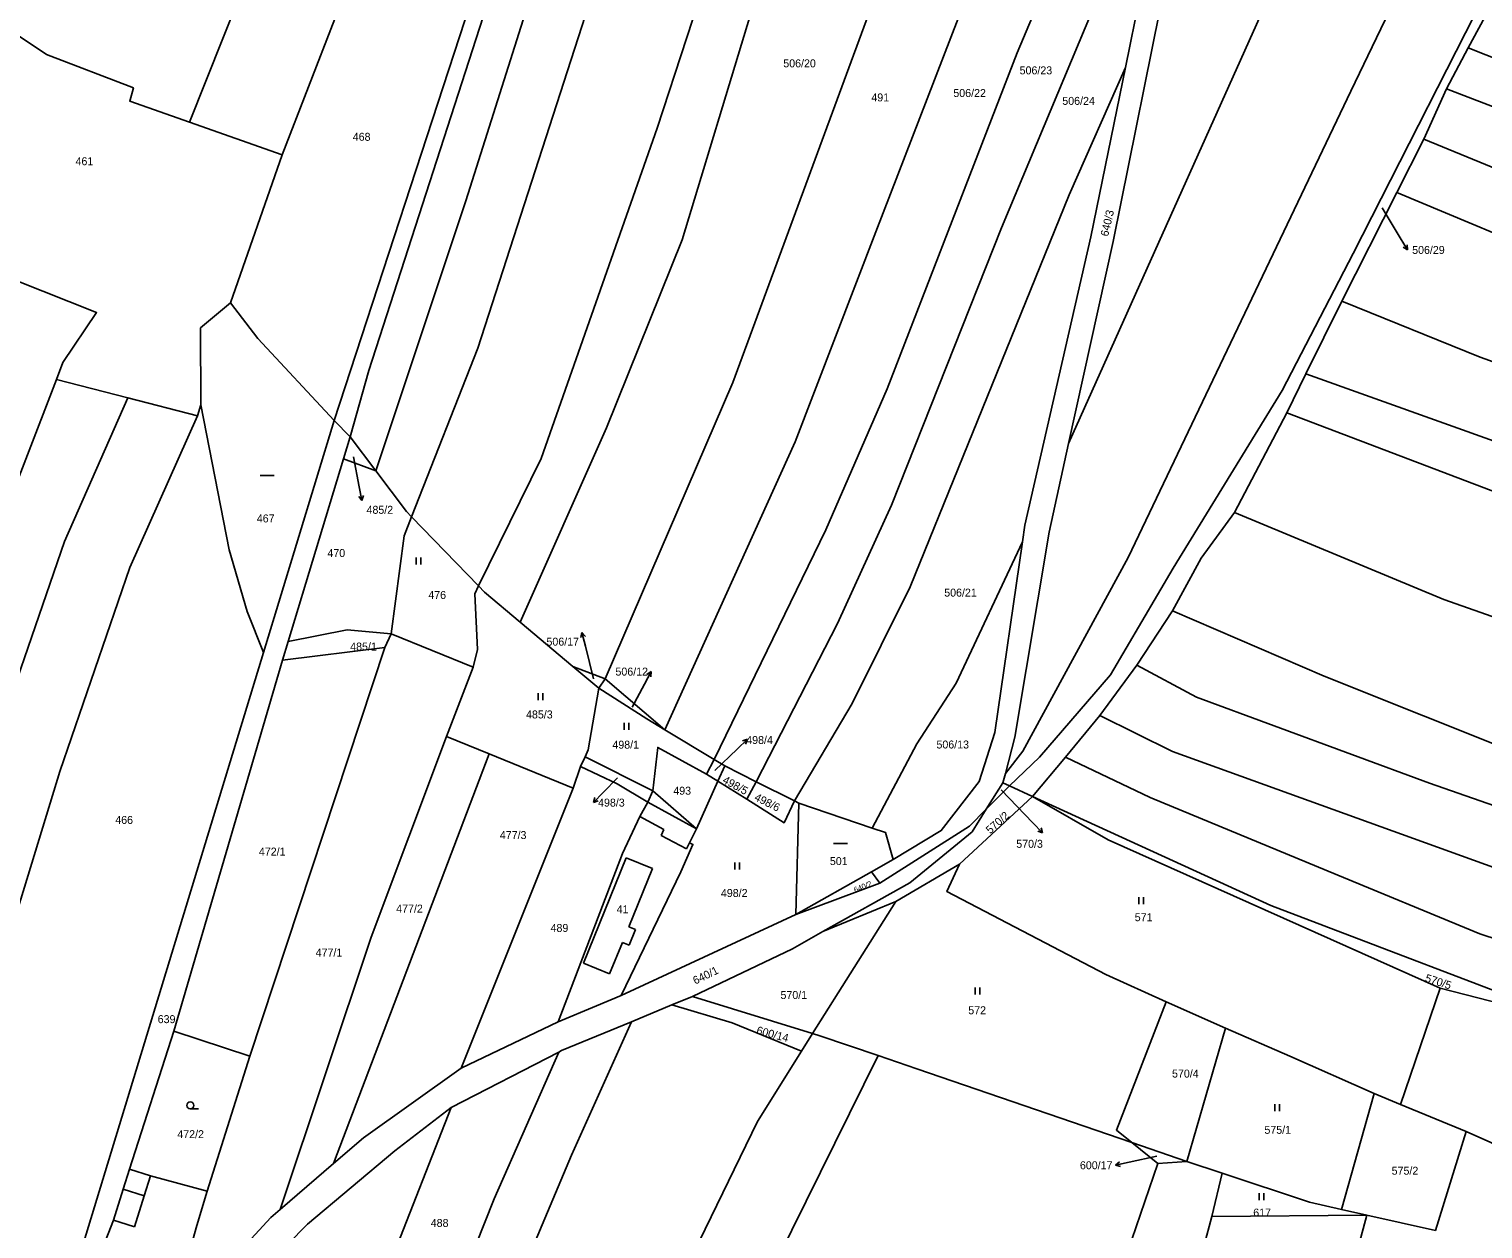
# Model space of a CAD drawing. Extents: x -746176 to -739709, y -1128407 to -1124482.
# Drawn here: x -742784.8 to -742474.2, y -1127139.9 to -1126883.6 of the extents above; entities that cross this region are included whole.
import ezdxf

# ---------------------------------------------------------------- set-up
doc = ezdxf.new("R2010")
doc.units = 0
for name, color, linetype in [('Hranice parcel', 7, 'Continuous'), ('Parcelní čísla', 7, 'Continuous'), ('Pop  PČ popisy', 7, 'Continuous'), ('Vnitřní kresba', 7, 'Continuous'), ('Značky kultur', 7, 'Continuous')]:
    doc.layers.add(name, color=color, linetype=linetype)

msp = doc.modelspace()

# ---------------------------------------------------------------- linework, layer by layer
at = {"layer": 'Hranice parcel'}
for p, q in [((-742550.57, -1126891.8), (-742539.32, -1126836.74)), ((-742465.86, -1126866.52), (-742477.38, -1126887.58)), ((-742481.95, -1126896.36), (-742477.38, -1126887.58)), ((-742486.79, -1126907.12), (-742481.95, -1126896.36)), ((-742730.7, -1126910.48), (-742750.49, -1126903.46)), ((-742492.57, -1126918.49), (-742486.79, -1126907.12)), ((-742741.76, -1126942.06), (-742730.7, -1126910.48)), ((-742504.35, -1126941.71), (-742492.57, -1126918.49)), ((-742512.02, -1126957.27), (-742504.35, -1126941.71)), ((-742516.09, -1126965.6), (-742512.02, -1126957.27)), ((-742778.92, -1126958.45), (-742763.72, -1126962.33)), ((-742763.72, -1126962.33), (-742748.81, -1126966.24)), ((-742748.81, -1126966.24), (-742748.07, -1126963.89)), ((-742719.6, -1126967.23), (-742734.68, -1127016.73)), ((-742716.17, -1126970.68), (-742719.6, -1126967.23)), ((-742527.24, -1126986.86), (-742516.09, -1126965.6)), ((-742717.6, -1126975.4), (-742716.17, -1126970.68)), ((-742710.71, -1126977.95), (-742716.17, -1126970.68)), ((-742729.41, -1127014.42), (-742717.6, -1126975.4)), ((-742710.71, -1126977.95), (-742717.6, -1126975.4)), ((-742688.81, -1127002.53), (-742703.1, -1126987.76)), ((-742668.63, -1127019.74), (-742679.87, -1127010.3)), ((-742548.14, -1127019.47), (-742540.51, -1127007.89)), ((-742707.46, -1127012.77), (-742708.78, -1127015.67)), ((-742707.46, -1127012.77), (-742689.92, -1127019.87)), ((-742734.68, -1127016.73), (-742781.25, -1127169.22)), ((-742737.64, -1127102.99), (-742708.78, -1127015.67)), ((-742730.63, -1127018.43), (-742729.41, -1127014.42)), ((-742708.78, -1127015.67), (-742730.63, -1127018.43)), ((-742730.63, -1127018.43), (-742753.9, -1127097.67)), ((-742695.58, -1127034.67), (-742689.92, -1127019.87)), ((-742663.1, -1127024.39), (-742668.63, -1127019.74)), ((-742661.75, -1127022.4), (-742668.63, -1127019.74)), ((-742556.03, -1127030.18), (-742548.14, -1127019.47)), ((-742661.75, -1127022.4), (-742663.1, -1127024.39)), ((-742661.75, -1127022.4), (-742648.95, -1127033.28)), ((-742563.37, -1127039.11), (-742556.03, -1127030.18)), ((-742686.48, -1127038.39), (-742695.58, -1127034.67)), ((-742638.43, -1127039.61), (-742648.95, -1127033.28)), ((-742719.74, -1127125.92), (-742686.48, -1127038.39)), ((-742668.53, -1127045.71), (-742686.48, -1127038.39)), ((-742666.98, -1127041.09), (-742668.53, -1127045.71)), ((-742666.98, -1127041.09), (-742666.02, -1127039.02)), ((-742666.02, -1127039.02), (-742651.5, -1127046.32)), ((-742640.1, -1127042.71), (-742638.43, -1127039.61)), ((-742636.14, -1127040.99), (-742638.43, -1127039.61)), ((-742637.62, -1127044.26), (-742636.14, -1127040.99)), ((-742629.44, -1127044.36), (-742636.14, -1127040.99)), ((-742570.42, -1127047.48), (-742563.37, -1127039.11)), ((-742637.62, -1127044.26), (-742642.23, -1127054.43)), ((-742637.62, -1127044.26), (-742640.1, -1127042.71)), ((-742631.47, -1127048.12), (-742637.62, -1127044.26)), ((-742631.47, -1127048.12), (-742629.44, -1127044.36)), ((-742621.26, -1127048.47), (-742629.44, -1127044.36)), ((-742576.74, -1127044.58), (-742580.29, -1127050.24)), ((-742576.22, -1127042.62), (-742576.74, -1127044.58)), ((-742576.74, -1127044.58), (-742575.31, -1127045.24)), ((-742668.53, -1127045.71), (-742692.49, -1127105.57)), ((-742651.5, -1127046.32), (-742652.6, -1127048.7)), ((-742642.23, -1127054.43), (-742651.5, -1127046.32)), ((-742586.05, -1127061.99), (-742570.42, -1127047.48)), ((-742575.31, -1127045.24), (-742580.29, -1127050.24)), ((-742575.31, -1127045.24), (-742570.42, -1127047.48)), ((-742620.33, -1127048.94), (-742621.26, -1127048.47)), ((-742620.96, -1127072.73), (-742620.33, -1127048.94)), ((-742620.33, -1127048.94), (-742604.64, -1127054.26)), ((-742600.22, -1127061), (-742604.82, -1127063.6)), ((-742599.65, -1127069.95), (-742586.05, -1127061.99)), ((-742604.82, -1127063.6), (-742620.96, -1127072.73)), ((-742603.07, -1127066.02), (-742620.96, -1127072.73)), ((-742603.07, -1127066.02), (-742604.82, -1127063.6)), ((-742658.33, -1127090.03), (-742620.96, -1127072.73)), ((-742617.44, -1127098.12), (-742599.65, -1127069.95)), ((-742599.65, -1127069.95), (-742615.18, -1127076.38)), ((-742647.45, -1127092.03), (-742643.05, -1127090.21)), ((-742643.05, -1127090.21), (-742617.44, -1127098.12)), ((-742529.16, -1127097), (-742541.89, -1127091.38)), ((-742483.35, -1127088.47), (-742491.78, -1127113.29)), ((-742483.35, -1127088.47), (-742452.64, -1127096.27)), ((-742656.1, -1127095.61), (-742647.45, -1127092.03)), ((-742763.33, -1127127.12), (-742753.9, -1127097.67)), ((-742753.9, -1127097.67), (-742737.64, -1127102.99)), ((-742692.49, -1127105.57), (-742671.78, -1127095.63)), ((-742537.43, -1127125.45), (-742529.16, -1127097)), ((-742617.44, -1127098.12), (-742619.79, -1127101.89)), ((-742737.64, -1127102.99), (-742746.73, -1127131.84)), ((-742694.65, -1127113.94), (-742671.65, -1127102.1)), ((-742504.39, -1127135.7), (-742497.42, -1127110.95)), ((-742497.42, -1127110.95), (-742491.78, -1127113.29)), ((-742694.65, -1127113.94), (-742722.13, -1127184.01)), ((-742491.78, -1127113.29), (-742477.79, -1127119.09)), ((-742477.79, -1127119.09), (-742484.3, -1127140.22)), ((-742444.54, -1127133.92), (-742477.79, -1127119.09)), ((-742549.17, -1127121.43), (-742543.65, -1127125.88)), ((-742549.17, -1127121.43), (-742537.43, -1127125.45)), ((-742537.43, -1127125.45), (-742543.65, -1127125.88)), ((-742537.43, -1127125.45), (-742529.93, -1127127.94)), ((-742719.74, -1127125.92), (-742731.14, -1127135.75)), ((-742529.93, -1127127.94), (-742532.11, -1127137.2)), ((-742532.11, -1127137.2), (-742498.96, -1127136.92)), ((-742498.96, -1127136.92), (-742504.39, -1127135.7)), ((-742498.96, -1127136.92), (-742484.3, -1127140.22))]:
    msp.add_line(p, q, dxfattribs=at)
for points in [[(-742561.23, -1126767.89), (-742567.77, -1126783.13), (-742587.89, -1126832.72), (-742634.42, -1126959.12), (-742661.75, -1127022.4)], [(-742679.87, -1127010.3), (-742661.43, -1126968.75), (-742645.29, -1126928.59), (-742630.66, -1126880.5), (-742621.29, -1126852.62), (-742599.04, -1126792.93), (-742588.76, -1126769.25)], [(-742648.95, -1127033.28), (-742621.1, -1126971.78), (-742603.91, -1126926.94), (-742554.63, -1126799.18), (-742540.06, -1126770.15)], [(-742688.81, -1127002.53), (-742675.39, -1126975.35), (-742650.59, -1126904.79), (-742637.92, -1126865.97), (-742628.71, -1126838.73), (-742613.44, -1126798.13), (-742604.44, -1126772.24)], [(-742703.1, -1126987.76), (-742688.91, -1126951.77), (-742648.33, -1126826.13), (-742639.39, -1126803.22), (-742629.18, -1126778.81)], [(-742638.43, -1127039.61), (-742614.56, -1126990.57), (-742601.46, -1126960.43), (-742573.73, -1126888.65), (-742536.1, -1126799.53), (-742527.67, -1126779.74)], [(-742710.71, -1126977.95), (-742691.49, -1126920.27), (-742659.71, -1126819.94), (-742646.21, -1126781.41)], [(-742719.6, -1126967.23), (-742690.51, -1126878.08), (-742694.48, -1126866.91), (-742676.36, -1126812.17), (-742671.59, -1126785.41)], [(-742716.17, -1126970.68), (-742712.23, -1126956.56), (-742687.03, -1126878.58), (-742688.27, -1126869.14), (-742663.45, -1126784.04)], [(-742562.72, -1126972.14), (-742511.64, -1126858.28), (-742475.66, -1126785.18)], [(-742730.7, -1126910.48), (-742713.83, -1126866.81), (-742706.14, -1126831.54), (-742708.37, -1126829.06), (-742696.43, -1126791.7)], [(-742576.22, -1127042.62), (-742572.46, -1127037.81), (-742549.96, -1126996.44), (-742502.42, -1126896.85), (-742478.65, -1126847.35), (-742462.47, -1126810.41), (-742451.42, -1126791.4)], [(-742750.49, -1126903.46), (-742732.76, -1126858.93), (-742706.72, -1126793.58)], [(-742431.72, -1126796.46), (-742469.95, -1126868.69), (-742501.91, -1126931.51), (-742517.1, -1126960.81), (-742540.36, -1126998.76), (-742553.75, -1127021.53), (-742568.92, -1127039.08), (-742575.31, -1127045.24)], [(-742629.44, -1127044.36), (-742612.06, -1127010.59), (-742600.55, -1126985.29), (-742577.05, -1126926.06), (-742554.59, -1126872.35), (-742539.32, -1126836.74)], [(-742750.49, -1126903.46), (-742763.27, -1126898.97), (-742762.5, -1126896.14), (-742781.04, -1126889), (-742799.57, -1126876.62), (-742824.58, -1126865.74)], [(-742541.56, -1126871.36), (-742553.22, -1126928.98), (-742562.72, -1126972.14)], [(-742477.38, -1126887.58), (-742416.04, -1126911.9), (-742348.05, -1126935.25), (-742114.93, -1127013.93), (-742085.96, -1127023.63)], [(-742550.57, -1126891.8), (-742562.56, -1126918.99), (-742596.53, -1127002.73), (-742608.98, -1127027.64), (-742621.26, -1127048.47)], [(-742572.58, -1126993.14), (-742572.06, -1126989.56), (-742557.96, -1126927.95), (-742550.57, -1126891.8)], [(-742089.28, -1127034.5), (-742293.25, -1126965), (-742398.92, -1126928.26), (-742481.95, -1126896.36)], [(-742486.79, -1126907.12), (-742444.87, -1126924.33), (-742397.83, -1126942.23), (-742288.59, -1126978.66), (-742195.26, -1127011.61), (-742092.54, -1127045.19)], [(-742492.57, -1126918.49), (-742455.79, -1126933.86), (-742390.03, -1126957.98), (-742252.16, -1127003.9), (-742129.68, -1127044.77), (-742095.98, -1127056.46)], [(-742778.92, -1126958.45), (-742777.55, -1126954.82), (-742770.36, -1126944.15), (-742810.76, -1126928.12)], [(-742748.07, -1126963.89), (-742748.16, -1126947.44), (-742741.76, -1126942.06)], [(-742741.76, -1126942.06), (-742735.91, -1126949.7), (-742719.6, -1126967.23)], [(-742504.35, -1126941.71), (-742474.75, -1126953.67), (-742378.88, -1126988.04), (-742204.08, -1127046.96), (-742100.58, -1127080.82), (-742076.73, -1127089.67), (-742044, -1127103.72)], [(-742512.02, -1126957.27), (-742426.6, -1126987.75), (-742322.02, -1127023.9), (-742152.02, -1127080.85), (-742092.77, -1127100.11), (-742049.6, -1127117.15)], [(-742842.98, -1127149.74), (-742815.95, -1127061.82), (-742792.49, -1126993.43), (-742778.92, -1126958.45)], [(-742828.27, -1127153.14), (-742812.1, -1127103.89), (-742795.18, -1127045), (-742777.21, -1126993.06), (-742763.72, -1126962.33)], [(-742734.68, -1127016.73), (-742738.19, -1127008), (-742742.04, -1126994.82), (-742748.07, -1126963.89)], [(-742813.25, -1127156.61), (-742778.25, -1127042.21), (-742763.25, -1126998.63), (-742748.81, -1126966.24)], [(-742516.09, -1126965.6), (-742463.84, -1126985.43), (-742374.91, -1127016.27), (-742226.88, -1127065.31), (-742153.9, -1127090.43), (-742091.98, -1127111.83), (-742053.72, -1127127.51)], [(-742562.72, -1126972.14), (-742566.88, -1126991.03), (-742574.16, -1127034.85), (-742576.22, -1127042.62)], [(-742703.1, -1126987.76), (-742704.16, -1126986.66), (-742710.71, -1126977.95)], [(-742707.46, -1127012.77), (-742704.66, -1126991.83), (-742703.1, -1126987.76)], [(-742540.51, -1127007.89), (-742534.38, -1126996.59), (-742527.24, -1126986.86)], [(-742527.24, -1126986.86), (-742482.52, -1127005.44), (-742410.26, -1127030.86), (-742263.45, -1127080.11), (-742124.08, -1127127.86), (-742062.93, -1127150.64)], [(-742572.58, -1126993.14), (-742586.73, -1127023.3), (-742595.13, -1127036.3), (-742604.64, -1127054.26)], [(-742600.22, -1127061), (-742589.93, -1127054.79), (-742581.78, -1127044.3), (-742578.46, -1127033.87), (-742572.58, -1126993.14)], [(-742689.92, -1127019.87), (-742689.01, -1127016.13), (-742689.59, -1127004.26), (-742688.81, -1127002.53)], [(-742679.87, -1127010.3), (-742687.53, -1127003.86), (-742688.81, -1127002.53)], [(-742540.51, -1127007.89), (-742508.14, -1127021.79), (-742465.67, -1127038.76), (-742304.51, -1127093.48), (-742186.57, -1127134.04), (-742101.64, -1127162.49), (-742071.1, -1127173.63)], [(-742729.41, -1127014.42), (-742716.86, -1127011.94), (-742707.46, -1127012.77)], [(-742548.14, -1127019.47), (-742535.36, -1127026.31), (-742485.61, -1127044.66), (-742396.17, -1127075.85), (-742237.29, -1127129.3), (-742102.44, -1127175.98), (-742075.64, -1127186.64)], [(-742663.1, -1127024.39), (-742665.33, -1127037.52), (-742666.02, -1127039.02)], [(-742648.95, -1127033.28), (-742652.83, -1127030.94), (-742663.1, -1127024.39)], [(-742556.03, -1127030.18), (-742540.54, -1127037.88), (-742464.14, -1127065.48), (-742257.87, -1127136.04), (-742181.95, -1127162.82), (-742111.16, -1127186.39), (-742079.42, -1127198.6)], [(-742731.14, -1127135.75), (-742711.74, -1127077.56), (-742695.58, -1127034.67)], [(-742651.5, -1127046.32), (-742650.49, -1127037.02), (-742640.1, -1127042.71)], [(-742652.6, -1127048.7), (-742659.18, -1127044.79), (-742666.98, -1127041.09)], [(-742081.6, -1127209.14), (-742129.12, -1127193.01), (-742202.75, -1127169.34), (-742345.7, -1127119.16), (-742474.83, -1127076.87), (-742507.28, -1127063.47), (-742545.28, -1127047.75), (-742563.37, -1127039.11)], [(-742570.42, -1127047.48), (-742519.53, -1127070.81), (-742452.64, -1127096.27)], [(-742570.42, -1127047.48), (-742554.29, -1127056.77), (-742483.35, -1127088.47)], [(-742652.6, -1127048.7), (-742654.28, -1127051.82), (-742658.01, -1127059.67), (-742671.78, -1127095.63)], [(-742621.26, -1127048.47), (-742623.51, -1127053.12), (-742631.47, -1127048.12)], [(-742615.18, -1127076.38), (-742596.61, -1127065.97), (-742583.33, -1127055.08), (-742580.29, -1127050.24)], [(-742580.29, -1127050.24), (-742583.91, -1127053.87), (-742603.07, -1127066.02)], [(-742658.33, -1127090.03), (-742645.55, -1127063.63), (-742642.98, -1127057.75), (-742643.7, -1127057.4), (-742642.23, -1127054.43)], [(-742604.64, -1127054.26), (-742601.82, -1127055.21), (-742600.22, -1127061)], [(-742586.05, -1127061.99), (-742588.7, -1127067.82), (-742554.78, -1127085.5), (-742541.89, -1127091.38)], [(-742643.05, -1127090.21), (-742621.7, -1127080.04), (-742615.18, -1127076.38)], [(-742671.78, -1127095.63), (-742663.55, -1127092.23), (-742658.33, -1127090.03)], [(-742541.89, -1127091.38), (-742552.48, -1127118.77), (-742549.17, -1127121.43)], [(-742619.79, -1127101.89), (-742634.59, -1127095.86), (-742647.45, -1127092.03)], [(-742656.1, -1127095.61), (-742668.92, -1127124.1), (-742695.82, -1127188.09)], [(-742671.65, -1127102.1), (-742671.07, -1127101.8), (-742656.1, -1127095.61)], [(-742529.16, -1127097), (-742515.45, -1127102.99), (-742497.42, -1127110.95)], [(-742603.37, -1127102.87), (-742615.85, -1127098.61), (-742617.44, -1127098.12)], [(-742706.71, -1127187.05), (-742685.41, -1127133.42), (-742671.65, -1127102.1)], [(-742662.31, -1127190.95), (-742647.78, -1127155.16), (-742629.16, -1127116.92), (-742619.79, -1127101.89)], [(-742644.1, -1127192.22), (-742631.06, -1127158.9), (-742603.37, -1127102.87)], [(-742603.37, -1127102.87), (-742595.15, -1127105.68), (-742549.17, -1127121.43)], [(-742692.49, -1127105.57), (-742713.34, -1127120.39), (-742719.74, -1127125.92)], [(-742738.13, -1127151.87), (-742725.34, -1127138.85), (-742706.66, -1127123.2), (-742694.65, -1127113.94)], [(-742773.17, -1127157.23), (-742769.01, -1127143.81), (-742766.77, -1127137.99), (-742764.69, -1127131.41), (-742763.33, -1127127.12)], [(-742746.73, -1127131.84), (-742758.85, -1127128.54), (-742763.33, -1127127.12)], [(-742543.65, -1127125.88), (-742554.78, -1127158.4), (-742562.37, -1127191.45), (-742566.48, -1127203.04)], [(-742504.39, -1127135.7), (-742511.23, -1127134.16), (-742529.93, -1127127.94)], [(-742746.73, -1127131.84), (-742748.92, -1127139.17), (-742751.52, -1127148.31), (-742756.51, -1127164.2)], [(-742731.14, -1127135.75), (-742733.12, -1127137.46), (-742746.45, -1127151.91), (-742756.51, -1127164.2)], [(-742553.15, -1127238.87), (-742547.82, -1127218.47), (-742536.99, -1127155.61), (-742532.11, -1127137.2)], [(-742523.75, -1127248.38), (-742518.59, -1127225.94), (-742507.29, -1127167.65), (-742498.96, -1127136.92)]]:
    msp.add_lwpolyline(points, dxfattribs=at)
at = {"layer": 'Pop  PČ popisy'}
for p, q in [((-742495.71, -1126921.8), (-742491.86, -1126928.21)), ((-742491.86, -1126928.21), (-742490.31, -1126930.78)), ((-742490.31, -1126930.78), (-742490.4, -1126929.67)), ((-742490.31, -1126930.78), (-742491.26, -1126930.18)), ((-742715.45, -1126974.96), (-742714.25, -1126981.35)), ((-742714.25, -1126981.35), (-742713.68, -1126984.3)), ((-742713.68, -1126984.3), (-742714.36, -1126983.41)), ((-742713.68, -1126984.3), (-742713.38, -1126983.22)), ((-742666.67, -1127012.46), (-742666.91, -1127013.55)), ((-742665.94, -1127015.37), (-742666.67, -1127012.46)), ((-742666.67, -1127012.46), (-742665.94, -1127013.31)), ((-742664.21, -1127022.41), (-742665.94, -1127015.37)), ((-742653.31, -1127023.49), (-742651.9, -1127020.84)), ((-742651.9, -1127020.84), (-742652.81, -1127021.49)), ((-742651.9, -1127020.84), (-742651.93, -1127021.96)), ((-742655.92, -1127028.43), (-742653.31, -1127023.49)), ((-742633.5, -1127037.38), (-742631.34, -1127035.29)), ((-742631.34, -1127035.29), (-742632.41, -1127035.63)), ((-742631.34, -1127035.29), (-742631.71, -1127036.35)), ((-742638.3, -1127041.94), (-742633.5, -1127037.38)), ((-742659.09, -1127043.5), (-742662.15, -1127046.66)), ((-742662.15, -1127046.66), (-742664.23, -1127048.82)), ((-742664.23, -1127048.82), (-742663.9, -1127047.75)), ((-742577.15, -1127046.1), (-742570.34, -1127053.11)), ((-742664.23, -1127048.82), (-742663.18, -1127048.45)), ((-742570.34, -1127053.11), (-742568.26, -1127055.27)), ((-742568.26, -1127055.27), (-742568.59, -1127054.2)), ((-742568.26, -1127055.27), (-742569.31, -1127054.9)), ((-742552.69, -1127126.26), (-742551.81, -1127125.57)), ((-742549.75, -1127125.64), (-742552.69, -1127126.26)), ((-742543.87, -1127124.36), (-742549.75, -1127125.64)), ((-742552.69, -1127126.26), (-742551.6, -1127126.55))]:
    msp.add_line(p, q, dxfattribs=at)
at = {"layer": 'Vnitřní kresba'}
for p, q in [((-742652.6, -1127048.7), (-742642.23, -1127054.43)), ((-742654.28, -1127051.82), (-742649.19, -1127054.59)), ((-742649.73, -1127055.83), (-742649.19, -1127054.59)), ((-742649.73, -1127055.83), (-742644.34, -1127058.7)), ((-742644.34, -1127058.7), (-742643.7, -1127057.4)), ((-742666.37, -1127083.14), (-742657.21, -1127060.61)), ((-742657.21, -1127060.61), (-742651.6, -1127062.89)), ((-742656.67, -1127075.36), (-742651.6, -1127062.89)), ((-742656.67, -1127075.36), (-742655.24, -1127075.94)), ((-742656.59, -1127079.28), (-742655.24, -1127075.94)), ((-742660.76, -1127085.42), (-742658.03, -1127078.7)), ((-742658.03, -1127078.7), (-742656.59, -1127079.28)), ((-742666.37, -1127083.14), (-742660.76, -1127085.42)), ((-742760.21, -1127132.83), (-742758.85, -1127128.54)), ((-742764.69, -1127131.41), (-742760.21, -1127132.83)), ((-742762.29, -1127139.41), (-742760.21, -1127132.83)), ((-742766.77, -1127137.99), (-742765.39, -1127138.43)), ((-742765.39, -1127138.43), (-742762.29, -1127139.41))]:
    msp.add_line(p, q, dxfattribs=at)
at = {"layer": 'Značky kultur'}
for p, q in [((-742735.42, -1126978.93), (-742732.42, -1126978.93)), ((-742702.11, -1126997.97), (-742702.11, -1126996.47)), ((-742701.11, -1126997.97), (-742701.11, -1126996.47)), ((-742676.05, -1127026.97), (-742676.05, -1127025.47)), ((-742675.05, -1127026.97), (-742675.05, -1127025.47)), ((-742657.63, -1127033.26), (-742657.63, -1127031.76)), ((-742656.63, -1127033.26), (-742656.63, -1127031.76)), ((-742612.97, -1127057.56), (-742609.97, -1127057.56)), ((-742634.04, -1127063.11), (-742634.04, -1127061.61)), ((-742633.04, -1127063.11), (-742633.04, -1127061.61)), ((-742547.69, -1127070.53), (-742547.69, -1127069.03)), ((-742546.69, -1127070.53), (-742546.69, -1127069.03)), ((-742582.67, -1127089.81), (-742582.67, -1127088.31)), ((-742581.67, -1127089.81), (-742581.67, -1127088.31)), ((-742750.34, -1127114.24), (-742748.59, -1127114.24)), ((-742518.62, -1127114.73), (-742518.62, -1127113.23)), ((-742517.62, -1127114.73), (-742517.62, -1127113.23)), ((-742522.03, -1127133.76), (-742522.03, -1127132.26)), ((-742521.03, -1127133.76), (-742521.03, -1127132.26))]:
    msp.add_line(p, q, dxfattribs=at)
msp.add_circle((-742750.34, -1127113.49), 0.75, dxfattribs=at)

# ---------------------------------------------------------------- texts
at = {"layer": 'Parcelní čísla'}
for s, p in [('506/20', (-742623.66, -1126891.77)), ('506/23', (-742573.17, -1126893.27)), ('491', (-742604.85, -1126899.05)), ('506/22', (-742587.33, -1126898.11)), ('506/24', (-742564.05, -1126899.79)), ('468', (-742715.64, -1126907.46)), ('461', (-742774.87, -1126912.68)), ('506/29', (-742489.31, -1126931.63)), ('485/2', (-742712.7, -1126987.13)), ('467', (-742736.14, -1126988.97)), ('470', (-742721.05, -1126996.36)), ('476', (-742699.5, -1127005.32)), ('506/21', (-742589.28, -1127004.82)), ('506/17', (-742674.26, -1127015.29)), ('485/1', (-742716.19, -1127016.34)), ('506/12', (-742659.52, -1127021.69)), ('485/3', (-742678.62, -1127030.84)), ('498/1', (-742660.17, -1127037.3)), ('498/4', (-742631.58, -1127036.3)), ('506/13', (-742590.94, -1127037.26)), ('498/3', (-742663.23, -1127049.67)), ('493', (-742647.16, -1127047.13)), ('466', (-742766.38, -1127053.37)), ('477/3', (-742684.22, -1127056.6)), ('570/3', (-742573.89, -1127058.47)), ('472/1', (-742735.69, -1127060.13)), ('501', (-742613.71, -1127062.16)), ('498/2', (-742636.99, -1127068.98)), ('477/2', (-742706.36, -1127072.31)), ('41', (-742659.27, -1127072.46)), ('571', (-742548.58, -1127074.15)), ('489', (-742673.38, -1127076.44)), ('477/1', (-742723.56, -1127081.69)), ('570/1', (-742624.26, -1127090.76)), ('639', (-742757.31, -1127095.92)), ('572', (-742584.14, -1127094.02)), ('570/4', (-742540.61, -1127107.55)), ('472/2', (-742753.12, -1127120.49)), ('575/1', (-742520.87, -1127119.56)), ('600/17', (-742560.29, -1127127.13)), ('575/2', (-742493.69, -1127128.29)), ('488', (-742698.98, -1127139.45)), ('617', (-742523.26, -1127137.24))]:
    msp.add_text(s, height=1.7, dxfattribs=at).set_placement(p)
for s, height, rotation, p in [('640/3', 1.7, 77, (-742554.27, -1126928)), ('498/5', 1.7, 331, (-742636.79, -1127044.49)), ('498/6', 1.7, 333, (-742629.99, -1127048.22)), ('570/2', 1.7, 42, (-742579.45, -1127055.61)), ('640/2', 1.19, 22, (-742608.31, -1127068.09)), ('640/1', 1.7, 26, (-742642.46, -1127087.71)), ('570/5', 1.7, 342, (-742486.68, -1127087)), ('600/14', 1.7, 345, (-742629.52, -1127098.19))]:
    msp.add_text(s, height=height, rotation=rotation, dxfattribs=at).set_placement(p)

doc.saveas('drawing.dxf')
